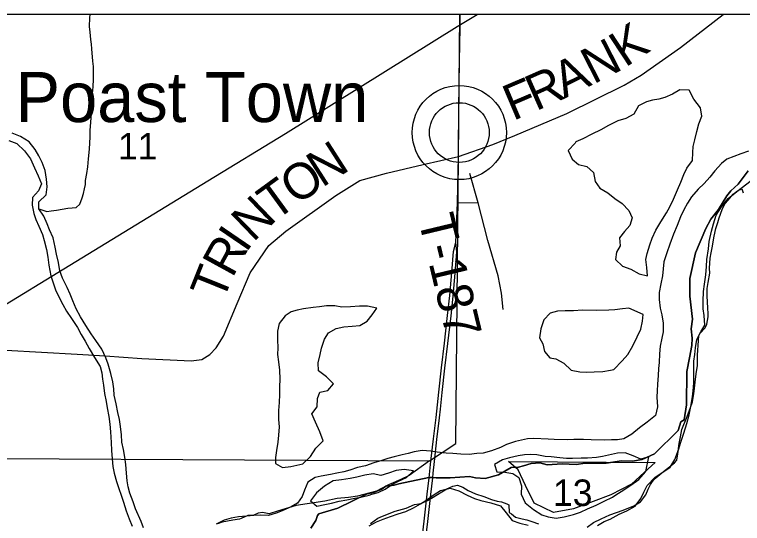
# Model space of a CAD drawing. Extents: x 0 to 34, y 0 to 22.
# Drawn here: x 17.545 to 18.696, y 19.432 to 20.236 of the extents above; entities that cross this region are included whole.
import ezdxf

# ---------------------------------------------------------------- set-up
doc = ezdxf.new("R2010")
doc.units = 0
for name, color, linetype in [('GM_X_County_Road', 7, 'Continuous'), ('GM_X_County_Road_Text', 7, 'Continuous'), ('GM_X_Major_River', 7, 'Continuous'), ('GM_X_Minor_River', 7, 'Continuous'), ('GM_X_Rail_Line', 7, 'Continuous'), ('GM_X_Section', 7, 'Continuous'), ('GM_X_Section_Text', 7, 'Continuous'), ('GM_X_State_Route', 7, 'Continuous'), ('GM_X_Township_Road', 7, 'Continuous'), ('GM_X_Township_Road_Text', 7, 'Continuous'), ('GM_X_Unincorporated', 7, 'Continuous'), ('GM_X_Unincorporated_Location', 7, 'Continuous'), ('GM_X_Unincorporated_Text', 7, 'Continuous'), ('SC_Scratch1', 7, 'Continuous'), ('SH_Border', 7, 'Continuous'), ('SH_Cut_Line', 7, 'Continuous')]:
    doc.layers.add(name, color=color, linetype=linetype)

msp = doc.modelspace()

# ---------------------------------------------------------------- linework, layer by layer
at = {"layer": 'GM_X_County_Road'}
for points in [[(18.247, 20.0121), (18.3011, 20.0306), (18.3362, 20.045), (18.4184, 20.08), (18.5086, 20.1246), (18.5357, 20.1402), (18.5976, 20.1841), (18.6652, 20.2361)], [(17.5319, 19.7058), (17.6443, 19.6997), (17.6885, 19.6969), (17.7465, 19.6927), (17.8248, 19.6888), (17.8413, 19.6909), (17.8543, 19.699), (17.8643, 19.7097), (17.8756, 19.728), (17.8975, 19.7794), (17.918, 19.8283), (17.9472, 19.8712), (17.9739, 19.8937), (18.0532, 19.9501), (18.0912, 19.9739), (18.1331, 19.9854), (18.1912, 19.9993), (18.247, 20.0121)]]:
    msp.add_lwpolyline(points, dxfattribs=at)
at = {"layer": 'GM_X_Major_River'}
for points in [[(18.693, 20.0162), (18.6712, 20.0077), (18.6625, 20.001), (18.652, 19.989), (18.6442, 19.9793), (18.6353, 19.9692), (18.6256, 19.9603), (18.6151, 19.9483), (18.6089, 19.9382), (18.603, 19.9276), (18.5978, 19.9167), (18.5926, 19.9031), (18.587, 19.8892), (18.581, 19.8733), (18.5762, 19.8597), (18.5717, 19.8457), (18.5703, 19.8344), (18.5694, 19.8233), (18.5668, 19.8108), (18.5643, 19.7968), (18.564, 19.7858), (18.5657, 19.7721), (18.5685, 19.7618), (18.5705, 19.7488), (18.5702, 19.7351), (18.5681, 19.7249), (18.5656, 19.7124), (18.5646, 19.6999), (18.5643, 19.6866), (18.563, 19.6767), (18.5628, 19.6661), (18.5617, 19.6524), (18.5607, 19.6414), (18.5605, 19.6315), (18.5614, 19.6163), (18.5584, 19.6027), (18.5449, 19.5923), (18.533, 19.5834), (18.5207, 19.5734), (18.5084, 19.5656), (18.4981, 19.5643), (18.4886, 19.5641), (18.4784, 19.5635), (18.4564, 19.564), (18.4443, 19.5646), (18.4295, 19.5645), (18.4188, 19.5643), (18.398, 19.5647), (18.3885, 19.5653), (18.3658, 19.5665), (18.3563, 19.5656), (18.3468, 19.5638), (18.3369, 19.5614), (18.3231, 19.5567), (18.3132, 19.5523), (18.2994, 19.5469), (18.286, 19.543), (18.2762, 19.5424), (18.264, 19.5411), (18.2507, 19.5414), (18.2379, 19.5424), (18.2273, 19.543), (18.2133, 19.5448), (18.2034, 19.5461), (18.1894, 19.5472), (18.1772, 19.5451), (18.1677, 19.5426), (18.1578, 19.5406), (18.1456, 19.5374), (18.1353, 19.5345), (18.1258, 19.5317), (18.1132, 19.5281), (18.0998, 19.5234), (18.0872, 19.5206), (18.0754, 19.5163), (18.0658, 19.5135), (18.0548, 19.5114), (18.0449, 19.5097), (18.03, 19.5066), (18.0205, 19.5045), (18.009, 19.4971), (18.0034, 19.4846), (17.9998, 19.4745), (17.9928, 19.4643), (17.9828, 19.4584), (17.9686, 19.4523), (17.9591, 19.4486), (17.9469, 19.4447), (17.9336, 19.4453), (17.9234, 19.4448), (17.9119, 19.4435), (17.8994, 19.4426), (17.888, 19.4405), (17.8769, 19.4373), (17.8643, 19.4311)], [(18.7052, 20.0205), (18.693, 20.0162)], [(18.687, 19.9568), (18.7095, 19.9737)], [(18.4669, 19.4288), (18.4773, 19.4351), (18.4868, 19.4391), (18.501, 19.4468), (18.5129, 19.4518), (18.5263, 19.4592), (18.5349, 19.4716), (18.5397, 19.4817), (18.5452, 19.4923), (18.5576, 19.505), (18.5714, 19.5142), (18.5814, 19.5212), (18.5889, 19.5332), (18.5945, 19.5483), (18.5985, 19.5604), (18.603, 19.5748), (18.6079, 19.5899), (18.6115, 19.6035), (18.6141, 19.6168), (18.6167, 19.6319), (18.618, 19.6418), (18.619, 19.6543), (18.6189, 19.6661), (18.6187, 19.6756), (18.619, 19.6885), (18.6203, 19.6988), (18.6217, 19.7094), (18.6234, 19.7227), (18.6301, 19.7347), (18.6361, 19.7456), (18.6352, 19.7608), (18.6339, 19.7711), (18.6334, 19.7833), (18.6341, 19.7985), (18.6358, 19.8103), (18.6377, 19.825), (18.6391, 19.8383), (18.6397, 19.8493), (18.6419, 19.866), (18.6433, 19.8774), (18.6466, 19.8937), (18.6499, 19.9054), (18.6544, 19.919), (18.6626, 19.9326), (18.6731, 19.9457), (18.687, 19.9568)], [(18.548, 19.5371), (18.535, 19.5339), (18.523, 19.5391), (18.5106, 19.5435), (18.4984, 19.5434), (18.4843, 19.5402), (18.4748, 19.5378), (18.4649, 19.5364), (18.4509, 19.5352), (18.441, 19.5354), (18.427, 19.5349), (18.4175, 19.5347), (18.4073, 19.536), (18.3933, 19.5375), (18.3838, 19.538), (18.3706, 19.5406), (18.3607, 19.5408), (18.3512, 19.5406), (18.3413, 19.5392), (18.3276, 19.5357), (18.3165, 19.5325), (18.3039, 19.5251), (18.3074, 19.5137), (18.3203, 19.513), (18.3328, 19.5109), (18.3425, 19.5046), (18.3464, 19.4916), (18.3462, 19.4783), (18.3523, 19.4649), (18.3654, 19.4544), (18.3789, 19.4457), (18.3887, 19.4425), (18.4015, 19.4407), (18.4141, 19.4428), (18.429, 19.4463), (18.4397, 19.4502), (18.4511, 19.455), (18.4645, 19.4612), (18.4772, 19.4674), (18.4902, 19.4736)], [(18.4902, 19.4736), (18.4941, 19.4765), (18.5098, 19.4861), (18.5194, 19.4924), (18.5321, 19.5017), (18.543, 19.5144), (18.548, 19.5371)], [(18.1759, 19.5151), (18.1611, 19.5173), (18.1486, 19.5156), (18.1363, 19.5113), (18.1241, 19.5081), (18.112, 19.5103), (18.0991, 19.5082), (18.0861, 19.5051), (18.0759, 19.503), (18.0622, 19.501), (18.0492, 19.4993), (18.0354, 19.4912), (18.0227, 19.4805), (18.0129, 19.4677), (18.023, 19.4596), (18.0356, 19.4623), (18.0463, 19.4644), (18.0584, 19.4672), (18.0703, 19.4693), (18.0832, 19.4721), (18.0927, 19.4738), (18.1061, 19.4769)], [(18.1061, 19.4769), (18.1099, 19.4784), (18.1202, 19.4812), (18.1309, 19.4863), (18.1413, 19.493), (18.1509, 19.4985), (18.1647, 19.5047), (18.1759, 19.5151)], [(18.1058, 19.4283), (18.1173, 19.4345), (18.128, 19.4389), (18.1395, 19.4432), (18.1517, 19.4475), (18.1639, 19.4511), (18.1758, 19.4566), (18.1869, 19.4632), (18.1969, 19.4694), (18.2069, 19.4769), (18.2185, 19.4842), (18.2337, 19.4877), (18.2473, 19.4837), (18.2608, 19.4769), (18.2721, 19.4714), (18.2823, 19.4685), (18.2981, 19.4648), (18.3132, 19.4599), (18.3224, 19.4487), (18.3317, 19.4368), (18.3437, 19.4327), (18.3573, 19.4294)]]:
    msp.add_lwpolyline(points, dxfattribs=at)
at = {"layer": 'GM_X_Minor_River'}
for points in [[(17.5839, 19.9294), (17.5966, 19.9251), (17.6034, 19.9262), (17.6117, 19.9272), (17.6208, 19.9287), (17.6295, 19.9301), (17.6363, 19.9308), (17.6427, 19.9311), (17.6488, 19.9368), (17.6523, 19.9466), (17.6546, 19.9534), (17.6562, 19.9606), (17.6574, 19.9674), (17.6578, 19.9742), (17.6598, 19.9848), (17.6614, 19.9958), (17.6622, 20.008), (17.6638, 20.0235), (17.6647, 20.0428), (17.6652, 20.0535), (17.6656, 20.0595), (17.666, 20.0663), (17.6669, 20.0804), (17.6678, 20.094), (17.6678, 20.1009), (17.6695, 20.1217), (17.6703, 20.1342), (17.67, 20.1479), (17.6701, 20.154), (17.6694, 20.1627), (17.6676, 20.1821), (17.6673, 20.1896), (17.6662, 20.1965), (17.6648, 20.2083), (17.6641, 20.2174), (17.6642, 20.231), (17.6648, 20.2361)], [(18.4314, 20.0329), (18.4201, 20.0213), (18.4267, 20.0079), (18.4364, 19.9994), (18.4496, 19.996), (18.4604, 19.9867), (18.4632, 19.9726), (18.4705, 19.9618), (18.4829, 19.9543), (18.4941, 19.9457), (18.5057, 19.9375), (18.5161, 19.9267), (18.5212, 19.9148), (18.5179, 19.9031), (18.5093, 19.8933), (18.5012, 19.8832), (18.5024, 19.8707), (18.4965, 19.8605), (18.4952, 19.8491), (18.5063, 19.8386), (18.5195, 19.8338), (18.5326, 19.8267), (18.5455, 19.8234), (18.5446, 19.8364), (18.5429, 19.849), (18.545, 19.8588), (18.5495, 19.8724), (18.5531, 19.883), (18.5591, 19.8954), (18.5669, 19.9086), (18.5755, 19.9228), (18.5811, 19.9326), (18.5866, 19.9447), (18.593, 19.9594), (18.5985, 19.9711), (18.6029, 19.9835), (18.6077, 19.9933), (18.6167, 20.0057), (18.6173, 20.0182), (18.6179, 20.0277), (18.6204, 20.0383), (18.6237, 20.0516), (18.6269, 20.0633), (18.6314, 20.0754), (18.6294, 20.0887), (18.619, 20.1026), (18.6117, 20.1165)], [(18.5966, 20.1171), (18.5854, 20.1101), (18.5732, 20.1051), (18.5636, 20.1026), (18.5537, 20.1009), (18.5442, 20.0984), (18.5316, 20.0918), (18.5241, 20.0786), (18.5114, 20.0717), (18.4988, 20.0681), (18.4843, 20.0608), (18.472, 20.0538), (18.4575, 20.0469), (18.4433, 20.0399), (18.4326, 20.0352), (18.4314, 20.0329)], [(18.6117, 20.1165), (18.5966, 20.1171)], [(17.6096, 19.8684), (17.6064, 19.8833), (17.6006, 19.896), (17.597, 19.9056), (17.5916, 19.9174), (17.5839, 19.9294), (17.5837, 19.94), (17.5953, 19.9512), (17.5971, 19.9641), (17.5962, 19.9763), (17.5938, 19.99), (17.5891, 20.0023), (17.584, 20.013), (17.5782, 20.023), (17.5686, 20.035), (17.5547, 20.0433), (17.5419, 20.0485)], [(17.5364, 20.0372), (17.5488, 20.0324), (17.5611, 20.0207), (17.5707, 20.008), (17.5768, 19.9942), (17.5826, 19.9811), (17.5881, 19.9689), (17.5833, 19.9575), (17.574, 19.9471), (17.5734, 19.9349), (17.5761, 19.9219), (17.579, 19.9124), (17.5837, 19.9016), (17.5895, 19.8886), (17.5923, 19.879)], [(17.5923, 19.879), (17.5962, 19.8649), (17.5982, 19.8527), (17.5995, 19.8401), (17.603, 19.8233), (17.6069, 19.8107), (17.6101, 19.8011), (17.6156, 19.7904), (17.6218, 19.7781), (17.6276, 19.7673), (17.6353, 19.7561), (17.6449, 19.7415), (17.6508, 19.7307), (17.657, 19.7203), (17.6636, 19.7084), (17.672, 19.6942), (17.6805, 19.6803), (17.6833, 19.67), (17.6846, 19.6601), (17.6859, 19.6506), (17.6876, 19.6376), (17.69, 19.6246), (17.692, 19.6147), (17.6944, 19.601), (17.6961, 19.5888), (17.697, 19.577), (17.6981, 19.5602), (17.6986, 19.5473), (17.6995, 19.534), (17.7008, 19.5221), (17.7028, 19.5118), (17.7067, 19.4985), (17.7103, 19.4874), (17.7139, 19.477), (17.7178, 19.4655), (17.7217, 19.4522), (17.7268, 19.4395), (17.7315, 19.428)], [(17.7492, 19.4254), (17.7453, 19.4354), (17.7366, 19.4553), (17.733, 19.4664), (17.7276, 19.4798), (17.7248, 19.4901), (17.7234, 19.4996), (17.7222, 19.5115), (17.7213, 19.5252), (17.7197, 19.537), (17.7176, 19.5488), (17.7152, 19.5606), (17.7143, 19.5721), (17.713, 19.5854), (17.7114, 19.5965), (17.7089, 19.6075), (17.7058, 19.6209), (17.703, 19.6346), (17.7021, 19.6449), (17.7008, 19.656), (17.6977, 19.669), (17.6934, 19.6839), (17.6898, 19.6938), (17.6833, 19.7073), (17.6741, 19.7211), (17.6667, 19.7319), (17.6579, 19.745), (17.6498, 19.7585), (17.6429, 19.7712), (17.6378, 19.7838), (17.6335, 19.7942), (17.6288, 19.8049), (17.6211, 19.8195), (17.6171, 19.831), (17.6151, 19.8444), (17.6116, 19.8577), (17.6096, 19.8684)], [(18.103, 19.7755), (18.0905, 19.7753), (18.0761, 19.7745), (18.0628, 19.7736), (18.0514, 19.7761), (18.0385, 19.776), (18.0275, 19.7743), (18.0176, 19.7733), (18.002, 19.7714), (17.9921, 19.7693), (17.9826, 19.7664), (17.973, 19.7601), (17.9636, 19.7482), (17.9611, 19.7357), (17.9608, 19.7224), (17.9613, 19.7098), (17.9611, 19.6988), (17.9628, 19.6873), (17.964, 19.6744), (17.9645, 19.6603), (17.9639, 19.6478), (17.9644, 19.636), (17.9634, 19.6231), (17.9627, 19.6105), (17.9628, 19.5961), (17.9634, 19.585), (17.9627, 19.5714), (17.9617, 19.5604), (17.9596, 19.5475), (17.9578, 19.5365), (17.9576, 19.5266)], [(18.1177, 19.7721), (18.103, 19.7755)], [(17.9576, 19.5266), (17.9689, 19.5207), (17.9818, 19.5223), (18.0009, 19.5265), (18.0129, 19.5381), (18.0215, 19.5508), (18.0331, 19.5628), (18.0277, 19.5766), (18.0208, 19.5919), (18.015, 19.6053), (18.0235, 19.6162), (18.0242, 19.6295), (18.0278, 19.6393), (18.0404, 19.6421), (18.0497, 19.6525), (18.0385, 19.6638), (18.0258, 19.6735), (18.0253, 19.6857), (18.0283, 19.699), (18.0307, 19.7088), (18.0352, 19.7232), (18.0415, 19.7333), (18.0538, 19.7403), (18.0659, 19.7427), (18.0789, 19.7436), (18.091, 19.7449), (18.1025, 19.7515), (18.1107, 19.7616), (18.1177, 19.7721)], [(18.5389, 19.762), (18.516, 19.7723), (18.5061, 19.7714), (18.4943, 19.7697), (18.4844, 19.7691), (18.4655, 19.7687), (18.4431, 19.7692), (18.4287, 19.7679), (18.4158, 19.7682), (18.4032, 19.7673), (18.3918, 19.7641), (18.3817, 19.7536), (18.3769, 19.7397), (18.3751, 19.7256), (18.3802, 19.716), (18.383, 19.7038), (18.3911, 19.6938), (18.401, 19.6924), (18.4133, 19.6853), (18.4252, 19.6745), (18.4385, 19.6715), (18.4487, 19.6713), (18.4616, 19.6718), (18.4749, 19.672), (18.4874, 19.6744)], [(18.4874, 19.6744), (18.4924, 19.6754), (18.5056, 19.6889), (18.5145, 19.6993), (18.5227, 19.7125), (18.5291, 19.7268), (18.535, 19.7392), (18.5376, 19.7517), (18.5389, 19.762)]]:
    msp.add_lwpolyline(points, dxfattribs=at)
at = {"layer": 'GM_X_Rail_Line'}
msp.add_lwpolyline([(16.6, 18.9508), (16.6112, 18.9745), (16.6341, 19.0224), (16.6602, 19.0697), (16.6847, 19.1097), (16.7161, 19.156), (16.7507, 19.2054), (16.7964, 19.2612), (16.8581, 19.3266), (16.9049, 19.3688), (16.9658, 19.4218), (17.0344, 19.4713), (17.1045, 19.5156), (17.2041, 19.5771), (17.2936, 19.6332), (17.851, 19.9733), (17.9736, 20.0481), (18.2449, 20.2171), (18.2765, 20.2361)], dxfattribs=at)
at = {"layer": 'GM_X_Section'}
for points in [[(18.4506, 19.4265), (18.4606, 19.4334), (18.4724, 19.4396), (18.4862, 19.4458), (18.5072, 19.4533), (18.524, 19.4601), (18.5348, 19.4663), (18.543, 19.4775), (18.5465, 19.4861), (18.5505, 19.4936), (18.5564, 19.5022), (18.571, 19.514), (18.5806, 19.5214), (18.5883, 19.5277), (18.5922, 19.5321), (18.5936, 19.5419), (18.5958, 19.5582), (18.5979, 19.5687), (18.6001, 19.5804), (18.6033, 19.5887), (18.6073, 19.5985), (18.6133, 19.6135), (18.6166, 19.6244), (18.6191, 19.6369), (18.6201, 19.6459), (18.6215, 19.6599), (18.6233, 19.672), (18.6246, 19.6811), (18.6246, 19.6981), (18.6262, 19.7212), (18.6268, 19.7287), (18.6287, 19.7325), (18.6369, 19.7414), (18.6396, 19.747), (18.6414, 19.7583), (18.6415, 19.7633), (18.641, 19.7727), (18.6402, 19.7913), (18.6401, 19.8031), (18.6414, 19.8129), (18.644, 19.8276), (18.6438, 19.8356), (18.6449, 19.8511), (18.6462, 19.8597), (18.6479, 19.8677), (18.651, 19.8858), (18.6535, 19.8982), (18.6567, 19.9076), (18.6588, 19.9148), (18.6636, 19.9283), (18.668, 19.9369), (18.673, 19.9429), (18.6812, 19.9526), (18.6881, 19.9577), (18.6945, 19.9609), (18.6971, 19.9547)], [(17.2257, 19.5361), (18.2013, 19.5311), (18.169, 19.5079), (18.156, 19.5013), (18.1365, 19.4931), (18.1173, 19.4832), (18.0872, 19.4752), (18.0732, 19.4732), (18.0553, 19.4713), (18.0356, 19.4672), (17.9907, 19.4606), (17.961, 19.4517), (17.948, 19.4475), (17.9371, 19.4492), (17.9302, 19.4486), (17.9234, 19.4454), (17.9143, 19.4448), (17.9035, 19.4401), (17.9009, 19.439), (17.8906, 19.4374), (17.8735, 19.4339), (17.8662, 19.4314)], [(18.1079, 19.4319), (18.1198, 19.4404), (18.1267, 19.4436), (18.147, 19.4515), (18.1641, 19.4565), (18.1775, 19.4619), (18.1843, 19.4629), (18.1889, 19.4643), (18.1981, 19.4682), (18.2069, 19.4734), (18.2207, 19.4822), (18.2288, 19.4869), (18.2383, 19.4909), (18.2452, 19.4926), (18.2538, 19.4894), (18.2624, 19.4843), (18.2741, 19.4787), (18.2872, 19.4747), (18.2992, 19.4699), (18.3083, 19.4674), (18.3151, 19.4661), (18.3233, 19.4629), (18.3263, 19.4617), (18.3272, 19.4496), (18.3306, 19.4472), (18.3369, 19.4422), (18.3478, 19.4393), (18.355, 19.438), (18.3629, 19.4352), (18.3734, 19.4315)]]:
    msp.add_lwpolyline(points, dxfattribs=at)
msp.add_lwpolyline([(18.5577, 19.5283), (18.5408, 19.5133), (18.5203, 19.4944), (18.488, 19.4771), (18.4596, 19.4666), (18.4285, 19.4554), (18.3973, 19.4493), (18.3667, 19.4643), (18.3528, 19.4921), (18.3411, 19.5166), (18.3259, 19.5299)], close=True, dxfattribs=at)
at = {"layer": 'GM_X_State_Route'}
for points in [[(18.2487, 20.163), (18.2494, 20.2154), (18.2496, 20.2361)], [(18.2471, 20.0221), (18.2477, 20.0864), (18.2487, 20.163)], [(18.2426, 19.8762), (18.2455, 19.9393), (18.247, 20.0121), (18.2471, 20.0221)], [(18.1883, 19.4001), (18.1927, 19.4355), (18.1977, 19.4783), (18.2006, 19.5042), (18.2035, 19.5305), (18.2076, 19.5656), (18.2115, 19.5995), (18.2159, 19.6395), (18.2202, 19.678), (18.2247, 19.717), (18.2298, 19.7606), (18.2331, 19.7921), (18.2364, 19.8284), (18.2391, 19.8619), (18.2426, 19.8762)], [(18.2185, 19.6128), (18.2213, 19.6388), (18.2256, 19.6773), (18.2302, 19.7163), (18.2352, 19.7599), (18.2385, 19.7914), (18.2419, 19.8277), (18.2445, 19.8612), (18.2426, 19.8762)], [(18.2071, 19.5113), (18.2092, 19.5298), (18.213, 19.5649), (18.2169, 19.5988), (18.2185, 19.6128)], [(18.1816, 19.2793), (18.1825, 19.2926), (18.1846, 19.3145), (18.1879, 19.3431), (18.1944, 19.3997), (18.1984, 19.435), (18.2033, 19.4778), (18.2062, 19.5041), (18.2071, 19.5113)]]:
    msp.add_lwpolyline(points, dxfattribs=at)
at = {"layer": 'GM_X_Township_Road'}
msp.add_line((18.2455, 19.9393), (18.2782, 19.9385), dxfattribs=at)
msp.add_lwpolyline([(18.3176, 19.7701), (18.3148, 19.796), (18.3099, 19.8231), (18.2936, 19.8794), (18.2782, 19.9385), (18.2647, 19.9848)], dxfattribs=at)
at = {"layer": 'GM_X_Unincorporated'}
msp.add_lwpolyline([(18.2493, 20.2361), (17.2319, 20.2361), (17.2257, 19.5361), (18.2013, 19.5311), (18.2428, 19.5586)], close=True, dxfattribs=at)
for radius in [0.0744, 0.0472]:
    msp.add_circle((18.2483, 20.0497), radius, dxfattribs=at)
at = {"layer": 'GM_X_Unincorporated_Location'}
msp.add_line((18.2483, 20.0497), (18.2483, 20.0497), dxfattribs=at)
at = {"layer": 'SC_Scratch1'}
for points in [[(19.257, 20.2361), (16.6, 20.2361), (16.6, 18.0794)], [(18.0139, 19.4246), (18.0218, 19.437), (18.024, 19.4449), (18.0262, 19.4472), (18.0565, 19.4561), (18.1027, 19.4788), (18.1125, 19.4808), (18.1247, 19.4856), (18.132, 19.4908), (18.1455, 19.4924), (18.1529, 19.4948), (18.2003, 19.5048), (18.206, 19.5046), (18.2118, 19.5042), (18.2339, 19.5042), (18.2644, 19.5064), (18.274, 19.5042), (18.2893, 19.5032), (18.3104, 19.509), (18.3304, 19.5206), (18.3416, 19.5209), (18.3495, 19.5231), (18.3619, 19.5267), (18.3758, 19.5277), (18.3873, 19.5247), (18.411, 19.5263), (18.4328, 19.525), (18.4471, 19.5276), (18.4806, 19.5272), (18.5048, 19.531), (18.5218, 19.5304), (18.5371, 19.5332), (18.5568, 19.5423), (18.5944, 19.5788), (18.5983, 19.5925), (18.6036, 19.5958), (18.6071, 19.6197), (18.608, 19.6721), (18.6121, 19.694), (18.6158, 19.7132), (18.6165, 19.7251), (18.6148, 19.7398), (18.6169, 19.7547), (18.6128, 19.791), (18.6126, 19.8189), (18.6216, 19.8596), (18.6378, 19.8981), (18.646, 19.913), (18.6578, 19.9282), (18.6709, 19.9496), (18.6773, 19.9578), (18.6889, 19.9682), (18.7046, 19.9893)], [(18.7046, 19.9893), (18.6889, 19.9682), (18.6773, 19.9578), (18.6709, 19.9496), (18.6578, 19.9282), (18.646, 19.913), (18.6378, 19.8981), (18.6216, 19.8596), (18.6126, 19.8189), (18.6128, 19.791), (18.6169, 19.7547), (18.6148, 19.7398), (18.6165, 19.7251), (18.6158, 19.7132), (18.6121, 19.694), (18.608, 19.6721), (18.6071, 19.6197), (18.6036, 19.5958), (18.5983, 19.5925), (18.5944, 19.5788), (18.5568, 19.5423), (18.5371, 19.5332), (18.5218, 19.5304), (18.5048, 19.531), (18.4806, 19.5272), (18.4471, 19.5276), (18.4328, 19.525), (18.411, 19.5263), (18.3873, 19.5247), (18.3758, 19.5277), (18.3619, 19.5267), (18.3495, 19.5231), (18.3416, 19.5209), (18.3304, 19.5206), (18.3104, 19.509), (18.2893, 19.5032), (18.274, 19.5042), (18.2644, 19.5064), (18.2339, 19.5042), (18.2118, 19.5042), (18.206, 19.5046), (18.2003, 19.5048), (18.1529, 19.4948), (18.1455, 19.4924), (18.132, 19.4908), (18.1247, 19.4856), (18.1125, 19.4808), (18.1027, 19.4788), (18.0565, 19.4561), (18.0262, 19.4472), (18.024, 19.4449), (18.0218, 19.437), (18.0139, 19.4246)]]:
    msp.add_lwpolyline(points, dxfattribs=at)
at = {"layer": 'SH_Border'}
msp.add_lwpolyline([(16.6, 20.2361), (16.6, 13.4361), (23.4, 13.4361), (23.4, 20.2361), (16.6, 20.2359)], dxfattribs=at)
at = {"layer": 'SH_Cut_Line'}
msp.add_lwpolyline([(19.257, 20.2361), (16.6, 20.2361), (16.6, 13.4361)], dxfattribs=at)

# ---------------------------------------------------------------- texts
at = {"layer": 'GM_X_County_Road_Text'}
for s, rotation, p in [('K', 33.3997, (18.5104, 20.1517)), ('N', 27.1309, (18.4601, 20.1254)), ('A', 26.0618, (18.4141, 20.103)), ('R', 23.822, (18.3692, 20.0831)), ('F', 23.0014, (18.3331, 20.0678)), ('N', 32.6948, (18.0313, 19.962)), ('O', 35.1794, (17.991, 19.9336)), ('T', 36.0668, (17.9568, 19.9087)), ('N', 43.9451, (17.9224, 19.8753)), ('I', 55.6756, (17.9112, 19.8584)), ('R', 61.3033, (17.8896, 19.8187)), ('T', 68.1417, (17.8745, 19.7809))]:
    msp.add_text(s, height=0.0568, rotation=rotation, dxfattribs=at).set_placement(p)
at = {"layer": 'GM_X_Section_Text'}
for s, p in [('11', (17.7089, 20.0072)), ('13', (18.3964, 19.4597))]:
    msp.add_text(s, height=0.04186, rotation=0, dxfattribs=at).set_placement(p)
at = {"layer": 'GM_X_Township_Road_Text'}
msp.add_text('T-187', height=0.05682, rotation=283.4933, dxfattribs=at).set_placement((18.183, 19.9137))
at = {"layer": 'GM_X_Unincorporated_Text'}
msp.add_text('Poast Town', height=0.07898, rotation=0, dxfattribs=at).set_placement((17.5469, 20.0663))

doc.saveas('drawing.dxf')
